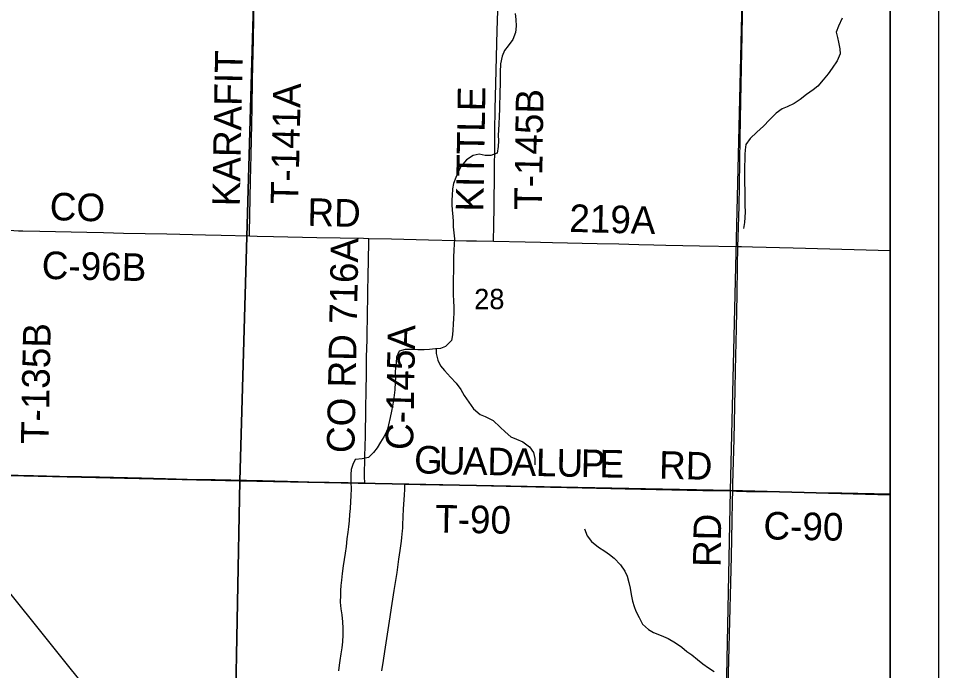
# Model space of a CAD drawing. Extents: x -38.1 to 35.9, y -2.7 to 28.5.
# Drawn here: x 23.615 to 25.51, y 15.586 to 16.929 of the extents above; entities that cross this region are included whole.
import ezdxf

# ---------------------------------------------------------------- set-up
doc = ezdxf.new("R2010")
doc.units = 0
for name, color, linetype in [('GM_X_City_Street_Text', 7, 'Continuous'), ('GM_X_Corporation', 7, 'Continuous'), ('GM_X_Major_River_Text', 7, 'Continuous'), ('GM_X_Minor_Lake', 7, 'Continuous'), ('GM_X_Minor_River', 7, 'Continuous'), ('GM_X_Section', 7, 'Continuous'), ('GM_X_Township', 7, 'Continuous'), ('GM_X_US_Route', 7, 'Continuous'), ('SH_Border', 7, 'Continuous'), ('SH_Data', 7, 'Continuous')]:
    doc.layers.add(name, color=color, linetype=linetype)

msp = doc.modelspace()

# ---------------------------------------------------------------- linework, layer by layer
at = {"layer": 'GM_X_City_Street_Text'}
for points in [[(23.5881, 16.4933), (23.6057, 16.4923), (23.6149, 16.4919), (23.6242, 16.4916), (23.659, 16.491), (23.756, 16.489), (23.7901, 16.488), (23.8311, 16.4871), (23.9206, 16.4851), (24.0001, 16.4833), (24.0324, 16.4826), (24.0907, 16.4813)], [(24.0907, 16.4813), (24.1063, 16.4809), (24.1399, 16.4799), (24.2294, 16.4782), (24.3257, 16.4762), (24.3366, 16.476)], [(24.3281, 15.9722), (24.3279, 15.985), (24.3284, 16.0273), (24.3295, 16.0683), (24.3306, 16.1242), (24.3311, 16.164), (24.3316, 16.1951), (24.3321, 16.2311), (24.3329, 16.2678), (24.3331, 16.2864), (24.3336, 16.3082), (24.3347, 16.3685), (24.3353, 16.3977), (24.3366, 16.4673), (24.3366, 16.476)], [(24.3366, 16.476), (24.3834, 16.475), (24.4592, 16.473), (24.5151, 16.4719), (24.5375, 16.4713), (24.5586, 16.4707), (24.5931, 16.47)], [(24.5931, 16.47), (24.6587, 16.4688), (24.6903, 16.4682), (24.7152, 16.4676), (24.8071, 16.4655), (24.8513, 16.4646), (24.8929, 16.4635), (24.9233, 16.4628), (24.9482, 16.4623), (24.983, 16.4615), (25.0178, 16.4609), (25.0968, 16.4594)], [(25.0968, 16.4594), (25.1038, 16.4592), (25.1271, 16.4585), (25.2103, 16.4563), (25.3364, 16.4529), (25.4101, 16.4509)], [(24.3281, 15.9722), (24.338, 15.9718), (24.347, 15.9715), (24.3705, 15.9711), (24.3943, 15.9705), (24.411, 15.9697)], [(24.3635, 15.5848), (24.3642, 15.5897), (24.3654, 15.5973), (24.371, 15.6338), (24.3791, 15.6875), (24.3847, 15.724), (24.3889, 15.7509), (24.3946, 15.7879), (24.3986, 15.8152), (24.4013, 15.8327), (24.4027, 15.8426), (24.4039, 15.8524), (24.4048, 15.8596), (24.4055, 15.8665), (24.4061, 15.8738), (24.4064, 15.8789), (24.4067, 15.8857), (24.4083, 15.9192), (24.41, 15.947), (24.4107, 15.9596), (24.411, 15.9697)], [(24.411, 15.9697), (24.4426, 15.9692), (24.4818, 15.9686), (24.5273, 15.9676), (24.5895, 15.9662), (24.7104, 15.9635), (24.7445, 15.9629), (24.7761, 15.9622), (24.8643, 15.9602), (25.0245, 15.9566), (25.0861, 15.9557)], [(25.0861, 15.9557), (25.0938, 15.9555), (25.1037, 15.9552), (25.1146, 15.9549), (25.1534, 15.9543), (25.2519, 15.9523), (25.3106, 15.9515), (25.4101, 15.95)]]:
    msp.add_lwpolyline(points, dxfattribs=at)
at = {"layer": 'GM_X_Corporation'}
msp.add_lwpolyline([(25.4101, 13.4873), (25.0847, 13.9186), (24.5478, 14.5412), (23.9622, 15.2897), (23.3945, 15.9977), (22.8429, 16.6968), (22.7771, 16.7664), (22.2793, 17.0387), (22.174, 17.095), (22.1183, 17.1348), (22.0806, 17.1798), (21.9636, 17.4041), (21.7841, 17.7749), (21.744, 17.8537), (21.7155, 17.9287), (21.6978, 17.9866), (21.6921, 18.0413), (21.6956, 18.1468), (21.7163, 18.7934), (21.7602, 19.7303), (21.7602, 19.7308)], dxfattribs=at)
at = {"layer": 'GM_X_Major_River_Text'}
for points in [[(24.0907, 16.4813), (24.0908, 16.4877), (24.093, 16.5953), (24.0941, 16.6477), (24.0961, 16.7446), (24.0973, 16.803), (24.0991, 16.8854), (24.1006, 16.9776), (24.1035, 17.1087), (24.1043, 17.1342), (24.1061, 17.2094), (24.1072, 17.2529), (24.1075, 17.2684), (24.1118, 17.4347), (24.1125, 17.4684), (24.113, 17.4883)], [(24.5931, 16.47), (24.5937, 16.5034), (24.5946, 16.5413), (24.5956, 16.6134), (24.5959, 16.6693), (24.5962, 16.6972), (24.597, 16.742), (24.598, 16.7954), (24.601, 16.9041), (24.6035, 16.9869), (24.6062, 17.086), (24.6074, 17.1356), (24.6082, 17.1742), (24.6094, 17.2333), (24.6102, 17.2587), (24.6108, 17.2885), (24.6112, 17.3109), (24.6122, 17.3469), (24.6128, 17.3792), (24.614, 17.422), (24.6152, 17.4782)], [(25.0968, 16.4594), (25.0973, 16.4777), (25.099, 16.5423), (25.0998, 16.5852), (25.1006, 16.6343), (25.1014, 16.6827), (25.1029, 16.7585), (25.104, 16.8269), (25.1052, 16.8946), (25.107, 16.9753), (25.1085, 17.0375), (25.1091, 17.0834), (25.11, 17.1201), (25.1113, 17.1922), (25.1119, 17.2214), (25.1132, 17.3121), (25.1142, 17.3599), (25.1155, 17.4308), (25.116, 17.4663)], [(25.0861, 15.9557), (25.0864, 15.9701), (25.0887, 16.0627), (25.0911, 16.1646), (25.0918, 16.2043), (25.0927, 16.2335), (25.0938, 16.2913), (25.0952, 16.3603), (25.0961, 16.4181), (25.0968, 16.4594)], [(23.5766, 15.9891), (23.5833, 15.9889), (23.6458, 15.9874), (23.6992, 15.9864), (23.7451, 15.9853), (23.7819, 15.9845), (23.811, 15.9839), (23.8685, 15.9826), (23.9179, 15.9815), (23.9626, 15.9803), (24.0198, 15.9792), (24.0844, 15.9779), (24.1173, 15.9771), (24.1689, 15.976), (24.213, 15.9748), (24.2547, 15.9739), (24.2938, 15.973), (24.31, 15.9726), (24.3281, 15.9722)], [(25.0623, 14.9477), (25.0633, 14.9868), (25.0657, 15.0663), (25.0674, 15.1464), (25.0685, 15.1961), (25.0706, 15.2881), (25.0728, 15.3763), (25.0745, 15.457), (25.0754, 15.5061), (25.0778, 15.6061), (25.0799, 15.6875), (25.0819, 15.767), (25.0833, 15.821), (25.0848, 15.8937), (25.0858, 15.9348), (25.0861, 15.9557)]]:
    msp.add_lwpolyline(points, dxfattribs=at)
at = {"layer": 'GM_X_Section'}
for points in [[(24.6379, 16.9394), (24.6392, 16.9269), (24.64, 16.9132), (24.6389, 16.8999), (24.6333, 16.8856), (24.6235, 16.8726), (24.6161, 16.8629), (24.6109, 16.8512), (24.6079, 16.8357), (24.6071, 16.8186), (24.6072, 16.808), (24.6069, 16.7932), (24.6062, 16.7784), (24.6054, 16.7431), (24.6047, 16.7268), (24.604, 16.712), (24.6037, 16.6987), (24.603, 16.6885), (24.6035, 16.6767), (24.6029, 16.665), (24.6011, 16.6517), (24.5877, 16.6467), (24.5763, 16.647), (24.5638, 16.6492), (24.5516, 16.6468), (24.5377, 16.638), (24.5268, 16.6246), (24.5204, 16.6126), (24.5156, 16.6017), (24.5112, 16.5889), (24.509, 16.5783), (24.5083, 16.5646), (24.5074, 16.5552), (24.5075, 16.5457), (24.5084, 16.5339), (24.5096, 16.521), (24.5102, 16.5111), (24.5103, 16.5001), (24.5119, 16.4875), (24.5128, 16.4753), (24.5122, 16.4639), (24.5115, 16.4518), (24.5112, 16.4374), (24.5113, 16.4279), (24.5107, 16.4169), (24.5109, 16.407), (24.5106, 16.3949), (24.5104, 16.3854), (24.5105, 16.3732), (24.5106, 16.3596), (24.5111, 16.3474), (24.5115, 16.3341), (24.5116, 16.3212), (24.511, 16.3117), (24.5104, 16.2988), (24.5097, 16.2878), (24.5087, 16.2772), (24.5066, 16.2659), (24.4945, 16.2536), (24.4842, 16.2493), (24.4739, 16.2484), (24.4617, 16.2472), (24.4503, 16.2463), (24.4374, 16.2462), (24.4245, 16.2469), (24.4112, 16.2472), (24.3993, 16.2437), (24.3934, 16.2313), (24.3927, 16.2195), (24.3914, 16.2097), (24.3911, 16.2002), (24.3913, 16.19), (24.3911, 16.1797), (24.3903, 16.1638), (24.3889, 16.1532), (24.3872, 16.1422), (24.3854, 16.1309)], [(25.3117, 16.9296), (25.3037, 16.9135), (25.2992, 16.901), (25.3016, 16.8896), (25.3037, 16.8801), (25.3064, 16.8663), (25.307, 16.8561), (25.3013, 16.8421), (25.2911, 16.8264), (25.2825, 16.8152), (25.2723, 16.8026), (25.2614, 16.7899), (25.2514, 16.7822), (25.2378, 16.7722), (25.2251, 16.7623), (25.2127, 16.7538), (25.1985, 16.7469), (25.1878, 16.7426), (25.1754, 16.7338), (25.1618, 16.7204), (25.1494, 16.7074), (25.1354, 16.6949), (25.1222, 16.6815), (25.1132, 16.6692), (25.1114, 16.6586), (25.1108, 16.6487), (25.1101, 16.6146), (25.1106, 16.6036), (25.1106, 16.588), (25.1108, 16.5774), (25.1108, 16.5637), (25.1112, 16.5439), (25.1116, 16.5306), (25.111, 16.5193), (25.11, 16.509), (25.1082, 16.4962)], [(24.4756, 16.2486), (24.4752, 16.2389), (24.4787, 16.2251), (24.4841, 16.2136), (24.4923, 16.204), (24.5049, 16.19), (24.5164, 16.178), (24.5264, 16.1648), (24.5329, 16.1525), (24.552, 16.1247), (24.5662, 16.1134), (24.5764, 16.1094), (24.5929, 16.101), (24.6071, 16.0874), (24.6171, 16.0773), (24.629, 16.0675), (24.6407, 16.0623), (24.6539, 16.0567), (24.6677, 16.0469), (24.6758, 16.0346), (24.6786, 16.0227), (24.6783, 16.0098)], [(24.3854, 16.1309), (24.3833, 16.1203), (24.3803, 16.1067), (24.3773, 16.0916), (24.374, 16.0802), (24.3673, 16.0675), (24.3606, 16.0559), (24.3538, 16.0446), (24.3464, 16.0346), (24.3359, 16.0249), (24.3226, 16.0222), (24.3085, 16.0206), (24.3033, 16.0101), (24.3004, 15.9999), (24.2994, 15.9893), (24.2994, 15.9734), (24.2999, 15.9605), (24.2992, 15.946), (24.2989, 15.9339), (24.2979, 15.9199), (24.2968, 15.9074), (24.2958, 15.8941), (24.2947, 15.882), (24.2933, 15.871), (24.2911, 15.8574), (24.2896, 15.8415), (24.2878, 15.8275), (24.286, 15.8146), (24.2838, 15.8014), (24.2816, 15.7859), (24.2805, 15.7722), (24.2791, 15.7612), (24.2785, 15.7506), (24.2779, 15.7408), (24.2776, 15.7267), (24.2792, 15.7126), (24.2808, 15.7008), (24.2824, 15.6864), (24.2828, 15.6727), (24.2829, 15.6594), (24.2822, 15.6446), (24.2808, 15.6325), (24.2786, 15.62), (24.2768, 15.6064), (24.2758, 15.5965), (24.2744, 15.5852)], [(24.7805, 15.8776), (24.7863, 15.8635), (24.7951, 15.8515), (24.8093, 15.8398), (24.8224, 15.8315), (24.8322, 15.8248), (24.8419, 15.8174), (24.8549, 15.8038), (24.8637, 15.7903), (24.8688, 15.7803), (24.8723, 15.767), (24.8747, 15.7555), (24.8767, 15.7422), (24.8798, 15.7284), (24.8829, 15.7177), (24.8865, 15.7078), (24.8931, 15.6947), (24.9004, 15.6816), (24.9123, 15.6704), (24.9232, 15.664), (24.9386, 15.6576), (24.9529, 15.6516), (24.9683, 15.6425), (24.9814, 15.6338), (24.9918, 15.6249), (25.0019, 15.6178), (25.0135, 15.6088), (25.0243, 15.5998), (25.0359, 15.5916), (25.0475, 15.5841)]]:
    msp.add_lwpolyline(points, dxfattribs=at)
at = {"layer": 'GM_X_US_Route'}
msp.add_lwpolyline([(25.4101, 13.9853), (25.4101, 18.4589), (22.0312, 18.5289)], dxfattribs=at)
for points in [[(23.083, 17.004), (24.0999, 16.9841), (24.0707, 15.9769), (23.0619, 15.9996)], [(24.0999, 16.9841), (25.105, 16.9645), (25.0807, 15.9564), (24.0707, 15.9769)], [(25.4101, 15.9479), (25.4101, 16.9566), (25.105, 16.9645), (25.0807, 15.9564)], [(23.0619, 15.9996), (24.0707, 15.9769), (24.0515, 14.9714), (23.0396, 14.9923)], [(24.0707, 15.9769), (25.0807, 15.9564), (25.0607, 14.9483), (24.0515, 14.9714)], [(25.4101, 14.9402), (25.4101, 15.9479), (25.0807, 15.9564), (25.0607, 14.9483)]]:
    msp.add_lwpolyline(points, close=True, dxfattribs=at)
at = {"layer": 'SH_Border'}
msp.add_line((25.4101, 19.7308), (25.4101, 12.9308), dxfattribs=at)
at = {"layer": 'SH_Data'}
msp.add_line((25.5101, 19.8308), (25.5101, 12.8308), dxfattribs=at)

# ---------------------------------------------------------------- texts
at = {"layer": 'GM_X_Minor_Lake'}
for s, height, rotation, p in [('KARAFIT', 0.05682, 88.8954, (24.0707, 16.5418)), ('T-141A', 0.05682, 88.698, (24.1911, 16.5462)), ('KITTLE', 0.05682, 89.019, (24.5724, 16.5307)), ('T-145B', 0.05682, 89.1156, (24.6927, 16.5343)), ('T-135B', 0.05682, 88.904, (23.6768, 16.052)), ('G', 0.0568, 357.4784, (24.4288, 15.9928)), ('U', 0.0568, 358.8336, (24.4802, 15.9905)), ('A', 0.0568, 358.8402, (24.5302, 15.9895)), ('D', 0.0568, 358.8415, (24.5802, 15.9885)), ('A', 0.0568, 358.8379, (24.6302, 15.9875)), ('L', 0.0568, 358.8402, (24.6802, 15.9865)), ('U', 0.0568, 358.8415, (24.7226, 15.9856)), ('P', 0.0568, 358.8406, (24.7726, 15.9846)), ('E', 0.0568, 358.8385, (24.811, 15.9838)), ('RD', 0.05682, 358.5367, (24.9338, 15.9812)), ('T-90', 0.05682, 358.9368, (24.4727, 15.8703)), ('RD', 0.05682, 89.023, (25.0609, 15.7986))]:
    msp.add_text(s, height=height, rotation=rotation, dxfattribs=at).set_placement(p)
at = {"layer": 'GM_X_Minor_River'}
msp.add_text('28', height=0.04186, rotation=0, dxfattribs=at).set_placement((24.5536, 16.3302))
at = {"layer": 'GM_X_Township'}
for s, rotation, p in [('CO', 358.5193, (23.6788, 16.5137)), ('RD', 358.6368, (24.2096, 16.5021)), ('219A', 358.4633, (24.7489, 16.4896)), ('CO RD 716A', 88.8825, (24.3067, 16.0333)), ('C-96B', 358.7172, (23.6624, 16.3927)), ('C-145A', 88.9353, (24.4277, 16.0397)), ('C-90', 358.9701, (25.1489, 15.856))]:
    msp.add_text(s, height=0.05682, rotation=rotation, dxfattribs=at).set_placement(p)

doc.saveas('drawing.dxf')
